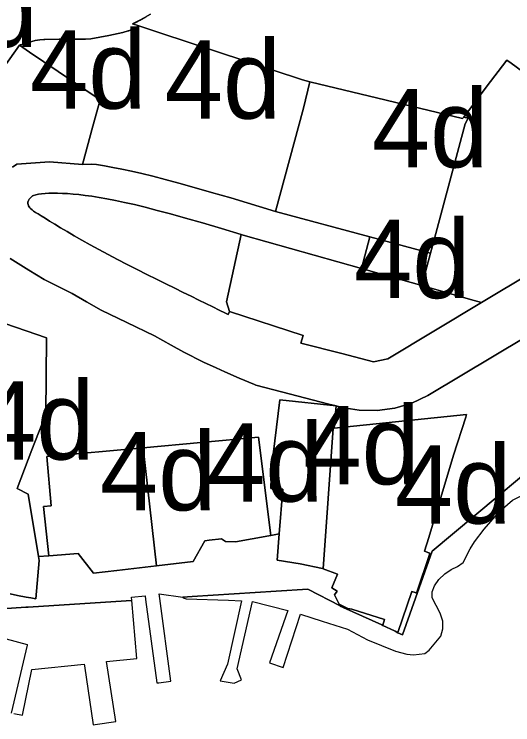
# Model space of a CAD drawing. Extents: x 598968 to 613553, y 4409678 to 4430833.
# Drawn here: x 609575.5 to 609651.9, y 4416518.9 to 4416627.8 of the extents above; entities that cross this region are included whole.
import ezdxf

# ---------------------------------------------------------------- set-up
doc = ezdxf.new("R2010")
doc.units = 0
for name, color, linetype in [('1', 7, 'Continuous'), ('4d. Sector de consolidació - ANNEX III A', 7, 'Continuous'), ('Sòl Rústic Protegit', 7, 'Continuous')]:
    doc.layers.add(name, color=color, linetype=linetype)

msp = doc.modelspace()

# ---------------------------------------------------------------- linework, layer by layer
at = {"layer": '1'}
for points in [[(609567.4547, 4416610.6238), (609576.3147, 4416623.0381), (609576.3095, 4416623.043), (609576.4075, 4416623.0863), (609576.63, 4416623.137), (609578.6984, 4416623.7418), (609579.4248, 4416623.8683), (609580.029, 4416623.9103), (609580.0702, 4416623.9132), (609580.1602, 4416623.9194), (609582.3659, 4416623.956), (609582.9874, 4416623.9624), (609585.1968, 4416623.9463), (609586.4258, 4416623.9499), (609587.2185, 4416624.0216), (609589.9866, 4416624.505), (609592.1312, 4416624.9676), (609592.9617, 4416625.2134), (609593.0344, 4416625.2439), (609593.1496, 4416625.2922), (609594.5791, 4416625.986), (609594.5763, 4416625.9869), (609593.639, 4416626.2956), (609593.6734, 4416626.3125), (609593.7077, 4416626.3295), (609593.7421, 4416626.3465), (609593.7764, 4416626.3635), (609593.8107, 4416626.3805), (609593.845, 4416626.3976), (609593.8793, 4416626.4147), (609593.9136, 4416626.4318), (609593.9479, 4416626.4489), (609593.9822, 4416626.466), (609594.0164, 4416626.4832), (609594.0507, 4416626.5004), (609594.0849, 4416626.5176), (609594.1191, 4416626.5348), (609594.1533, 4416626.5521), (609594.1875, 4416626.5694), (609594.2217, 4416626.5867), (609594.2559, 4416626.604), (609594.29, 4416626.6214), (609594.3242, 4416626.6387), (609594.3583, 4416626.6561), (609594.3925, 4416626.6736), (609594.4265, 4416626.691), (609594.4606, 4416626.7085), (609594.4947, 4416626.7259), (609594.5288, 4416626.7434), (609594.5628, 4416626.761), (609594.5969, 4416626.7785), (609594.631, 4416626.7961), (609594.665, 4416626.8137), (609594.699, 4416626.8313), (609594.7296, 4416626.8472), (609594.7601, 4416626.8631), (609594.7906, 4416626.879), (609594.821, 4416626.8951), (609594.8515, 4416626.9111), (609594.8819, 4416626.9273), (609594.9123, 4416626.9435), (609594.9426, 4416626.9597), (609594.9729, 4416626.976), (609595.0032, 4416626.9923), (609595.0335, 4416627.0087), (609595.0637, 4416627.0252), (609595.094, 4416627.0417), (609595.1241, 4416627.0582), (609595.1543, 4416627.0748), (609595.1844, 4416627.0915), (609595.2145, 4416627.1082), (609595.2446, 4416627.1249), (609595.2746, 4416627.1418), (609595.3046, 4416627.1586), (609595.3346, 4416627.1756), (609595.3645, 4416627.1925), (609595.3944, 4416627.2096), (609595.4243, 4416627.2266), (609595.4542, 4416627.2438), (609595.484, 4416627.2609), (609595.5138, 4416627.2782), (609595.5436, 4416627.2955), (609595.5733, 4416627.3128), (609595.603, 4416627.3302), (609595.6327, 4416627.3476), (609595.7265, 4416627.4029), (609595.8202, 4416627.4583), (609595.914, 4416627.5137), (609596.0077, 4416627.5691), (609596.1014, 4416627.6246), (609596.195, 4416627.6802), (609596.2887, 4416627.7358), (609596.3823, 4416627.7915)], [(609654.8714, 4416588.2506), (609647.1301, 4416583.6069), (609632.7817, 4416574.9996), (609630.5686, 4416574.5177), (609625.7231, 4416575.7708), (609619.4367, 4416577.3966), (609619.7632, 4416578.5569), (609608.5094, 4416582.2155), (609608.5118, 4416582.2088), (609608.2856, 4416581.7501), (609608.281, 4416581.7524), (609607.8614, 4416581.9593), (609606.9058, 4416582.431), (609605.9088, 4416582.9234), (609604.8643, 4416583.4396), (609603.766, 4416583.9827), (609602.6075, 4416584.5554), (609601.3828, 4416585.1608), (609600.0855, 4416585.8021), (609598.7135, 4416586.4804), (609597.2813, 4416587.1902), (609595.8074, 4416587.9246), (609594.3105, 4416588.6765), (609592.8091, 4416589.4386), (609591.3218, 4416590.204), (609589.8672, 4416590.9656), (609588.464, 4416591.716), (609587.1286, 4416592.4486), (609585.8686, 4416593.1565), (609584.6897, 4416593.8332), (609583.5975, 4416594.4723), (609582.5976, 4416595.0672), (609581.6955, 4416595.6112), (609580.8969, 4416596.0978), (609580.2074, 4416596.5207), (609579.6296, 4416596.8759), (609579.1543, 4416597.1712), (609578.7693, 4416597.4169), (609578.4623, 4416597.6235), (609578.2213, 4416597.8014), (609578.034, 4416597.961), (609577.8883, 4416598.1128), (609577.772, 4416598.2672), (609577.6765, 4416598.4327), (609577.6079, 4416598.6113), (609577.5759, 4416598.8025), (609577.5903, 4416599.0064), (609577.6608, 4416599.2228), (609577.7971, 4416599.4515), (609578.009, 4416599.6924), (609578.3061, 4416599.9453), (609578.3227, 4416599.9594), (609578.422, 4416599.9986), (609578.7879, 4416600.1045), (609579.2094, 4416600.1928), (609579.6861, 4416600.263), (609580.2172, 4416600.3149), (609580.8019, 4416600.3484), (609581.4393, 4416600.3632), (609582.1285, 4416600.359), (609582.8688, 4416600.3356), (609583.6592, 4416600.2927), (609584.5004, 4416600.2296), (609585.3984, 4416600.1435), (609586.3605, 4416600.0308), (609587.3944, 4416599.8882), (609588.5075, 4416599.7122), (609589.7071, 4416599.4996), (609591.0007, 4416599.247), (609592.3958, 4416598.9507), (609593.9047, 4416598.6062), (609595.5588, 4416598.2039), (609597.3947, 4416597.7323), (609599.4489, 4416597.1806), (609601.7576, 4416596.5378), (609604.3572, 4416595.7925), (609607.2844, 4416594.9339), (609610.2871, 4416594.0369), (609610.5754, 4416593.9508), (609628.7036, 4416588.8211), (609630.0116, 4416593.6698), (609615.5296, 4416597.5762), (609608.6755, 4416599.6237), (609605.7217, 4416600.4901), (609603.0889, 4416601.2449), (609600.7399, 4416601.899), (609598.637, 4416602.4638), (609596.7436, 4416602.95), (609595.0239, 4416603.3684), (609593.4435, 4416603.7292), (609591.9713, 4416604.0418), (609590.5947, 4416604.3107), (609589.306, 4416604.5392), (609588.0982, 4416604.7299), (609587.3602, 4416604.8317), (609585.9739, 4416604.7377), (609580.9157, 4416605.1521), (609575.8705, 4416604.8067), (609575.2248, 4416604.3272)], [(609572.5147, 4416580.915), (609580.4185, 4416578.1773), (609580.3386, 4416566.5115), (609578.1931, 4416561.0117), (609575.9348, 4416555.1182), (609577.6016, 4416554.2512), (609579.2009, 4416544.7001), (609580.8089, 4416544.8178), (609579.9535, 4416552.3418), (609581.1746, 4416552.4547), (609580.4719, 4416560.0341), (609595.2779, 4416561.3673), (609612.9173, 4416562.9557), (609614.8119, 4416547.9126), (609616.1098, 4416548.15), (609616.6483, 4416555.0034), (609614.7968, 4416555.1034), (609614.9132, 4416558.2424), (609616.2163, 4416568.6805), (609624.8251, 4416567.77), (609623.7273, 4416568.0539), (609616.4519, 4416569.9354), (609612.5202, 4416570.9522), (609612.3376, 4416571.0291), (609609.9794, 4416572.0382), (609607.7555, 4416573.0081), (609606.4658, 4416573.5786), (609604.5137, 4416574.4905), (609601.4864, 4416576.0107), (609599.5618, 4416577.0649), (609596.9662, 4416578.5086), (609592.7317, 4416580.5327), (609588.8218, 4416582.4189), (609586.5556, 4416583.7326), (609584.3507, 4416585.0084), (609581.934, 4416586.2114), (609580.0802, 4416587.1569), (609577.7521, 4416588.5585), (609574.8461, 4416590.3301)], [(609574.8461, 4416590.3301), (609577.7521, 4416588.5585), (609580.0802, 4416587.1569), (609581.934, 4416586.2114), (609584.3507, 4416585.0084), (609586.5556, 4416583.7326), (609588.8218, 4416582.4189), (609592.7317, 4416580.5327), (609596.9662, 4416578.5086), (609599.5618, 4416577.0649), (609601.4864, 4416576.0107), (609604.5137, 4416574.4905), (609606.4658, 4416573.5786), (609607.7555, 4416573.0081), (609609.9794, 4416572.0382), (609612.3376, 4416571.0291), (609612.5202, 4416570.9522), (609616.4519, 4416569.9354), (609623.7273, 4416568.0539), (609624.8251, 4416567.77), (609625.6893, 4416567.5465), (609628.3784, 4416567.0883), (609631.106, 4416567.0422), (609633.8092, 4416567.4089), (609636.4259, 4416568.1802), (609638.8957, 4416569.3383), (609658.9753, 4416581.3834)], [(609658.9753, 4416581.3834), (609638.8957, 4416569.3383), (609636.4259, 4416568.1802), (609633.8092, 4416567.4089), (609631.106, 4416567.0422), (609628.3784, 4416567.0883), (609625.6893, 4416567.5465), (609624.8251, 4416567.77), (609624.5548, 4416564.3563), (609644.8353, 4416566.4566), (609644.6945, 4416566.0451), (609642.8286, 4416560.2248), (609639.0508, 4416547.586), (609638.3917, 4416545.4922), (609639.0473, 4416545.2325), (609639.2009, 4416545.1717), (609637.166, 4416539.0778), (609636.9539, 4416539.1557), (609636.4545, 4416539.3391), (609634.309, 4416533.0221), (609634.3078, 4416533.0187), (609634.9908, 4416532.6923), (609639.5289, 4416545.5331), (609662.9024, 4416565.0291)], [(609662.9024, 4416565.0291), (609639.5289, 4416545.5331), (609634.9908, 4416532.6923), (609634.3078, 4416533.0187), (609633.8725, 4416533.2267), (609633.7683, 4416533.2768), (609631.9805, 4416534.1431), (609631.824, 4416534.2189), (609625.9016, 4416536.8833), (609625.4649, 4416537.0945), (609625.4534, 4416537.1173), (609620.5115, 4416539.697), (609615.6477, 4416539.3846), (609602.7531, 4416538.5565), (609601.3486, 4416538.4662), (609601.5376, 4416538.2898), (609601.8294, 4416538.2169), (609608.3578, 4416538.0018), (609610.3198, 4416537.897), (609608.2044, 4416528.2141), (609607.0754, 4416525.6431), (609609.2244, 4416525.2672), (609610.3274, 4416525.8162), (609609.6604, 4416527.4871), (609611.9973, 4416537.797), (609617.4088, 4416536.4227), (609614.6363, 4416528.4162), (609616.7133, 4416527.6593), (609619.3452, 4416535.8737), (609622.6892, 4416534.8023), (609626.5602, 4416533.5764), (609629.6371, 4416531.9434), (609633.9311, 4416530.2005), (609635.6591, 4416529.7181), (609636.7081, 4416529.6031), (609638.433, 4416529.8386), (609639.116, 4416530.3206), (609640.876, 4416532.4646), (609641.204, 4416533.5926), (609641.174, 4416534.7706), (609640.797, 4416536.0256), (609639.558, 4416538.3515), (609639.549, 4416539.2695), (609639.931, 4416540.2185), (609640.563, 4416541.1615), (609641.477, 4416542.0235), (609642.444, 4416542.7055), (609643.4549, 4416543.1805), (609644.3249, 4416543.7765), (609645.3879, 4416545.8695), (609646.0359, 4416546.9325), (609647.5439, 4416548.8785), (609649.9048, 4416551.6155), (609651.8898, 4416553.3375), (609655.6998, 4416555.2086)], [(609573.594, 4416536.6848), (609577.2541, 4416536.919), (609577.6487, 4416536.9444), (609592.6227, 4416537.9059), (609593.5184, 4416537.9633), (609593.479, 4416538.4354), (609595.549, 4416538.6755), (609595.6263, 4416538.0988), (609597.339, 4416525.3159), (609597.6384, 4416525.3565), (609599.479, 4416525.606), (609597.7865, 4416538.2374), (609597.6889, 4416538.9656), (609601.3486, 4416538.4662), (609602.7531, 4416538.5565), (609615.6477, 4416539.3846), (609620.5115, 4416539.697), (609625.4534, 4416537.1173), (609625.4649, 4416537.0945), (609625.9016, 4416536.8833), (609631.824, 4416534.2189), (609631.9805, 4416534.1431), (609631.982, 4416534.1478), (609632.2664, 4416535.0545), (609627.2359, 4416536.6255), (609626.6059, 4416536.7472), (609626.3025, 4416536.8943), (609625.3099, 4416537.4022), (609624.5948, 4416538.8206), (609624.9798, 4416539.4046), (609624.1804, 4416539.8707), (609625.0596, 4416541.9816), (609622.8607, 4416542.8156), (609622.7391, 4416542.8618), (609619.2997, 4416543.5708), (609615.7946, 4416544.1382), (609616.1098, 4416548.15), (609614.8119, 4416547.9126), (609614.5164, 4416547.8586), (609609.4192, 4416546.9262), (609607.8939, 4416546.9795), (609607.2552, 4416547.3992), (609605.3914, 4416547.2075), (609604.6902, 4416547.0994), (609602.9282, 4416543.9008), (609597.3087, 4416543.2575), (609591.2097, 4416542.5593), (609587.622, 4416542.1487), (609585.2968, 4416545.1464), (609580.8089, 4416544.8178), (609579.2009, 4416544.7001), (609579.3087, 4416544.056), (609578.8067, 4416538.185), (609578.0166, 4416538.3342), (609577.2971, 4416538.4701), (609575.994, 4416538.7269), (609574.8796, 4416538.9578)], [(609575.4106, 4416520.6332), (609576.7395, 4416520.3753), (609578.1994, 4416527.3752), (609586.2292, 4416528.1954), (609586.2665, 4416527.9403), (609587.5892, 4416518.9057), (609587.8987, 4416518.9513), (609591.0492, 4416519.4158), (609589.6492, 4416528.6156), (609594.259, 4416529.0757), (609593.5184, 4416537.9633), (609592.6227, 4416537.9059), (609577.6487, 4416536.9444), (609577.2541, 4416536.919), (609573.594, 4416536.6848)], [(609570.4296, 4416533.0848), (609577.4794, 4416531.215), (609577.4494, 4416531.0859), (609575.0396, 4416520.7052)]]:
    msp.add_lwpolyline(points, dxfattribs=at)
for points in [[(609610.2871, 4416594.0369), (609607.2844, 4416594.9339), (609604.3572, 4416595.7925), (609601.7576, 4416596.5378), (609599.4489, 4416597.1806), (609597.3947, 4416597.7323), (609595.5588, 4416598.2039), (609593.9047, 4416598.6062), (609592.3958, 4416598.9507), (609591.0007, 4416599.247), (609589.7071, 4416599.4996), (609588.5075, 4416599.7122), (609587.3944, 4416599.8882), (609586.3605, 4416600.0308), (609585.3984, 4416600.1435), (609584.5004, 4416600.2296), (609583.6592, 4416600.2927), (609582.8688, 4416600.3356), (609582.1285, 4416600.359), (609581.4393, 4416600.3632), (609580.8019, 4416600.3484), (609580.2172, 4416600.3149), (609579.6861, 4416600.263), (609579.2094, 4416600.1928), (609578.7879, 4416600.1045), (609578.422, 4416599.9986), (609578.3227, 4416599.9594), (609578.3061, 4416599.9453), (609578.009, 4416599.6924), (609577.7971, 4416599.4515), (609577.6608, 4416599.2228), (609577.5903, 4416599.0064), (609577.5759, 4416598.8025), (609577.6079, 4416598.6113), (609577.6765, 4416598.4327), (609577.772, 4416598.2672), (609577.8883, 4416598.1128), (609578.034, 4416597.961), (609578.2213, 4416597.8014), (609578.4623, 4416597.6235), (609578.7693, 4416597.4169), (609579.1543, 4416597.1712), (609579.6296, 4416596.8759), (609580.2074, 4416596.5207), (609580.8969, 4416596.0978), (609581.6955, 4416595.6112), (609582.5976, 4416595.0672), (609583.5975, 4416594.4723), (609584.6897, 4416593.8332), (609585.8686, 4416593.1565), (609587.1286, 4416592.4486), (609588.464, 4416591.716), (609589.8672, 4416590.9656), (609591.3218, 4416590.204), (609592.8091, 4416589.4386), (609594.3105, 4416588.6765), (609595.8074, 4416587.9246), (609597.2813, 4416587.1902), (609598.7135, 4416586.4804), (609600.0855, 4416585.8021), (609601.3828, 4416585.1608), (609602.6075, 4416584.5554), (609603.766, 4416583.9827), (609604.8643, 4416583.4396), (609605.9088, 4416582.9234), (609606.9058, 4416582.431), (609607.8614, 4416581.9593), (609608.281, 4416581.7524), (609608.2856, 4416581.7501), (609608.5118, 4416582.2088), (609608.5094, 4416582.2155), (609608.0352, 4416583.7194), (609608.0328, 4416583.726), (609610.2859, 4416594.0315)], [(609639.3018, 4416591.1638), (609630.0116, 4416593.6698), (609628.7036, 4416588.8211), (609632.1506, 4416587.8456), (609637.6036, 4416586.3025), (609637.9885, 4416586.1937)]]:
    msp.add_lwpolyline(points, close=True, dxfattribs=at)
at = {"layer": '4d. Sector de consolidació - ANNEX III A'}
for points in [[(609620.8143, 4416617.4444), (609620.8081, 4416617.4459), (609619.698, 4416617.7142), (609597.7893, 4416624.9288), (609594.5791, 4416625.986), (609593.1496, 4416625.2922), (609593.0344, 4416625.2439), (609592.9617, 4416625.2134), (609592.1312, 4416624.9676), (609589.9866, 4416624.505), (609587.2185, 4416624.0216), (609586.4258, 4416623.9499), (609585.1968, 4416623.9463), (609582.9874, 4416623.9624), (609582.3659, 4416623.956), (609580.1602, 4416623.9194), (609580.0702, 4416623.9132), (609580.029, 4416623.9103), (609579.4248, 4416623.8683), (609578.6984, 4416623.7418), (609576.63, 4416623.137), (609576.4075, 4416623.0863), (609576.3095, 4416623.043), (609576.3147, 4416623.0381), (609577.8266, 4416621.9666), (609577.8326, 4416621.9622), (609588.6462, 4416614.6437), (609587.558, 4416610.6202), (609585.9686, 4416604.743), (609585.9755, 4416604.7435), (609585.9739, 4416604.7377), (609587.3602, 4416604.8317), (609588.0982, 4416604.7299), (609589.306, 4416604.5392), (609590.5947, 4416604.3107), (609591.9713, 4416604.0418), (609593.4435, 4416603.7292), (609595.0239, 4416603.3684), (609596.7436, 4416602.95), (609598.637, 4416602.4638), (609600.7399, 4416601.899), (609603.0889, 4416601.2449), (609605.7217, 4416600.4901), (609608.6755, 4416599.6237), (609615.5296, 4416597.5762), (609619.8275, 4416613.4097)], [(609644.3853, 4416612.0299), (609644.204, 4416611.79), (609620.8143, 4416617.4444), (609619.8275, 4416613.4097), (609615.5296, 4416597.5762), (609630.0116, 4416593.6698), (609639.3018, 4416591.1638), (609640.1007, 4416594.1877), (609644.5874, 4416610.9632), (609645.0904, 4416611.8347)], [(609628.7036, 4416588.8211), (609610.5754, 4416593.9508), (609610.2871, 4416594.0369), (609610.2859, 4416594.0315), (609608.0328, 4416583.726), (609608.0352, 4416583.7194), (609608.5094, 4416582.2155), (609619.7632, 4416578.5569), (609619.4367, 4416577.3966), (609625.7231, 4416575.7708), (609630.5686, 4416574.5177), (609632.7817, 4416574.9996), (609647.1301, 4416583.6069), (609645.4379, 4416584.0857), (609637.9885, 4416586.1937), (609637.6036, 4416586.3025), (609632.1506, 4416587.8456)], [(609624.8251, 4416567.77), (609616.2163, 4416568.6805), (609614.9132, 4416558.2424), (609614.7968, 4416555.1034), (609616.6483, 4416555.0034), (609616.1098, 4416548.15), (609615.7946, 4416544.1382), (609619.2997, 4416543.5708), (609622.7391, 4416542.8618), (609622.8607, 4416542.8156), (609624.3997, 4416564.3402), (609624.5548, 4416564.3563)], [(609634.3078, 4416533.0187), (609634.309, 4416533.0221), (609636.4545, 4416539.3391), (609636.9539, 4416539.1557), (609637.166, 4416539.0778), (609639.2009, 4416545.1717), (609639.0473, 4416545.2325), (609638.3917, 4416545.4922), (609639.0508, 4416547.586), (609642.8286, 4416560.2248), (609644.6945, 4416566.0451), (609644.8353, 4416566.4566), (609624.5548, 4416564.3563), (609624.3997, 4416564.3402), (609622.8607, 4416542.8156), (609625.0596, 4416541.9816), (609624.1804, 4416539.8707), (609624.9798, 4416539.4046), (609624.5948, 4416538.8206), (609625.3099, 4416537.4022), (609626.3025, 4416536.8943), (609626.6059, 4416536.7472), (609627.2359, 4416536.6255), (609632.2664, 4416535.0545), (609631.982, 4416534.1478), (609631.9805, 4416534.1431), (609633.7683, 4416533.2768), (609633.8725, 4416533.2267)], [(609614.8119, 4416547.9126), (609612.9173, 4416562.9557), (609595.2779, 4416561.3673), (609597.3087, 4416543.2575), (609602.9282, 4416543.9008), (609604.6902, 4416547.0994), (609605.3914, 4416547.2075), (609607.2552, 4416547.3992), (609607.8939, 4416546.9795), (609609.4192, 4416546.9262), (609614.5164, 4416547.8586)], [(609597.3087, 4416543.2575), (609595.2779, 4416561.3673), (609580.4719, 4416560.0341), (609581.1746, 4416552.4547), (609579.9535, 4416552.3418), (609580.8089, 4416544.8178), (609585.2968, 4416545.1464), (609587.622, 4416542.1487), (609591.2097, 4416542.5593)]]:
    msp.add_lwpolyline(points, close=True, dxfattribs=at)
for points in [[(609575.2248, 4416604.3272), (609575.8705, 4416604.8067), (609580.9157, 4416605.1521), (609585.9739, 4416604.7377), (609585.9755, 4416604.7435), (609585.9686, 4416604.743), (609587.558, 4416610.6202), (609588.6462, 4416614.6437), (609577.8326, 4416621.9622), (609577.8266, 4416621.9666), (609576.3147, 4416623.0381), (609567.4547, 4416610.6238)], [(609670.9266, 4416606.1567), (609651.6368, 4416620.2893), (609650.9872, 4416620.7652), (609647.8459, 4416616.6088), (609644.3853, 4416612.0299), (609645.0904, 4416611.8347), (609644.5874, 4416610.9632), (609640.1007, 4416594.1877), (609639.3018, 4416591.1638), (609637.9885, 4416586.1937), (609645.4379, 4416584.0857), (609647.1301, 4416583.6069), (609654.8714, 4416588.2506)], [(609574.8796, 4416538.9578), (609575.994, 4416538.7269), (609577.2971, 4416538.4701), (609578.0166, 4416538.3342), (609578.8067, 4416538.185), (609579.3087, 4416544.056), (609579.2009, 4416544.7001), (609577.6016, 4416554.2512), (609575.9348, 4416555.1182), (609578.1931, 4416561.0117), (609580.3386, 4416566.5115), (609580.4185, 4416578.1773), (609572.5147, 4416580.915)]]:
    msp.add_lwpolyline(points, dxfattribs=at)
at = {"layer": 'Sòl Rústic Protegit'}
msp.add_lwpolyline([(609596.3823, 4416627.7915), (609596.2887, 4416627.7358), (609596.195, 4416627.6802), (609596.1014, 4416627.6246), (609596.0077, 4416627.5691), (609595.914, 4416627.5137), (609595.8202, 4416627.4583), (609595.7265, 4416627.4029), (609595.6327, 4416627.3476), (609595.603, 4416627.3302), (609595.5733, 4416627.3128), (609595.5436, 4416627.2955), (609595.5138, 4416627.2782), (609595.484, 4416627.2609), (609595.4542, 4416627.2438), (609595.4243, 4416627.2266), (609595.3944, 4416627.2096), (609595.3645, 4416627.1925), (609595.3346, 4416627.1756), (609595.3046, 4416627.1586), (609595.2746, 4416627.1418), (609595.2446, 4416627.1249), (609595.2145, 4416627.1082), (609595.1844, 4416627.0915), (609595.1543, 4416627.0748), (609595.1241, 4416627.0582), (609595.094, 4416627.0417), (609595.0637, 4416627.0252), (609595.0335, 4416627.0087), (609595.0032, 4416626.9923), (609594.9729, 4416626.976), (609594.9426, 4416626.9597), (609594.9123, 4416626.9435), (609594.8819, 4416626.9273), (609594.8515, 4416626.9111), (609594.821, 4416626.8951), (609594.7906, 4416626.879), (609594.7601, 4416626.8631), (609594.7296, 4416626.8472), (609594.699, 4416626.8313), (609594.665, 4416626.8137), (609594.631, 4416626.7961), (609594.5969, 4416626.7785), (609594.5628, 4416626.761), (609594.5288, 4416626.7434), (609594.4947, 4416626.7259), (609594.4606, 4416626.7085), (609594.4265, 4416626.691), (609594.3925, 4416626.6736), (609594.3583, 4416626.6561), (609594.3242, 4416626.6387), (609594.29, 4416626.6214), (609594.2559, 4416626.604), (609594.2217, 4416626.5867), (609594.1875, 4416626.5694), (609594.1533, 4416626.5521), (609594.1191, 4416626.5348), (609594.0849, 4416626.5176), (609594.0507, 4416626.5004), (609594.0164, 4416626.4832), (609593.9822, 4416626.466), (609593.9479, 4416626.4489), (609593.9136, 4416626.4318), (609593.8793, 4416626.4147), (609593.845, 4416626.3976), (609593.8107, 4416626.3805), (609593.7764, 4416626.3635), (609593.7421, 4416626.3465), (609593.7077, 4416626.3295), (609593.6734, 4416626.3125), (609593.639, 4416626.2956), (609594.5763, 4416625.9869), (609594.5791, 4416625.986), (609597.7893, 4416624.9288), (609619.698, 4416617.7142), (609620.8081, 4416617.4459), (609620.8143, 4416617.4444), (609644.204, 4416611.79), (609644.3853, 4416612.0299), (609647.8459, 4416616.6088), (609650.9872, 4416620.7652), (609651.6368, 4416620.2893), (609670.9266, 4416606.1567)], dxfattribs=at)

# ---------------------------------------------------------------- texts
at = {"layer": '4d. Sector de consolidació - ANNEX III A'}
for p in [(609561.2693, 4416622.7421), (609577.9106, 4416613.3113), (609598.5619, 4416611.7811), (609630.31, 4416604.3041), (609627.5814, 4416584.2773), (609569.9487, 4416559.55), (609619.8109, 4416555.7481), (609605.0449, 4416553.1066), (609588.6311, 4416551.758), (609633.848, 4416549.7376)]:
    msp.add_text('4d', height=12, dxfattribs=at).set_placement(p)

doc.saveas('drawing.dxf')
